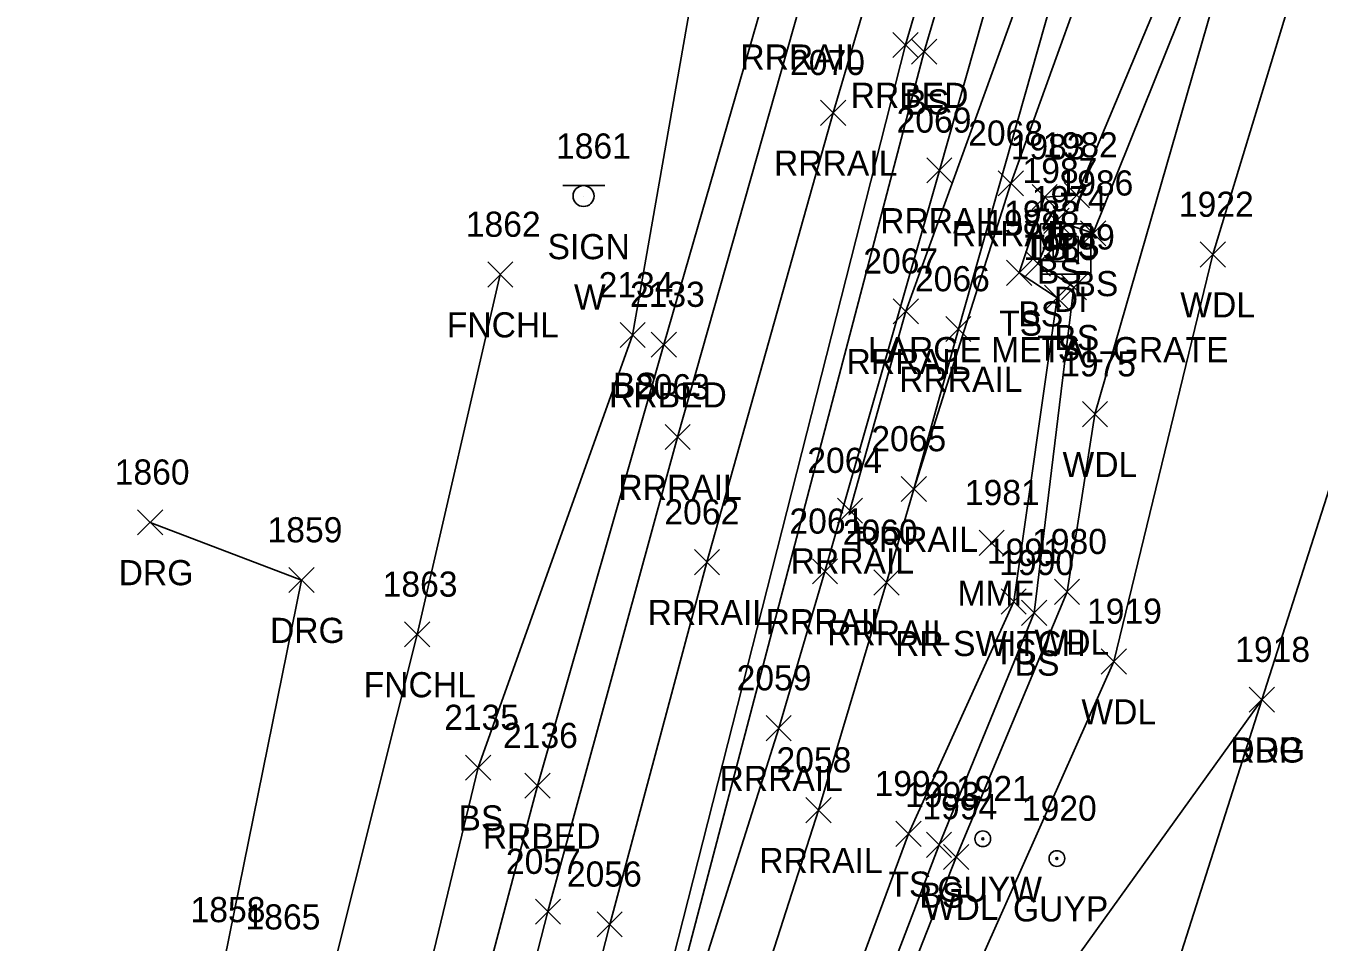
# Model space of a CAD drawing. Extents: x 1769141 to 1770817, y 735471 to 742405.
# Drawn here: x 1770206.1 to 1770309, y 742108.4 to 742181.3 of the extents above; entities that cross this region are included whole.
import ezdxf

# ---------------------------------------------------------------- set-up
doc = ezdxf.new("R2010")
doc.units = 0
for name, color, linetype in [('D_A', 7, 'Continuous'), ('D_C', 7, 'Continuous'), ('D_I', 7, 'Continuous'), ('DS', 7, 'Continuous'), ('L_A', 7, 'Continuous'), ('L_C', 7, 'Continuous'), ('L_I', 7, 'Continuous'), ('L_TIC', 7, 'Continuous'), ('LAWA', 7, 'Continuous'), ('LELB', 7, 'Continuous'), ('LFNC', 7, 'Continuous'), ('P_A', 7, 'Continuous'), ('P_I', 7, 'Continuous'), ('P_TIC', 7, 'Continuous'), ('PET', 7, 'Continuous'), ('R_A', 7, 'Continuous'), ('R_I', 7, 'Continuous'), ('R_TIC', 7, 'Continuous'), ('RDG', 7, 'Continuous'), ('RR', 7, 'Continuous'), ('RRB', 7, 'Continuous'), ('S_A', 7, 'Continuous'), ('S_C', 7, 'Continuous'), ('S_I', 7, 'Continuous'), ('SSGN', 7, 'Continuous'), ('U_A', 7, 'Continuous'), ('U_I', 7, 'Continuous'), ('UPGW', 7, 'Continuous')]:
    doc.layers.add(name, color=color, linetype=linetype)

msp = doc.modelspace()

# ---------------------------------------------------------------- linework, layer by layer
at = {"layer": 'DS'}
for p, q in [((1770286.8, 742165.54), (1770290.8, 742165.54)), ((1770286.8, 742161.54), (1770286.8, 742165.54)), ((1770290.8, 742165.54), (1770290.8, 742161.54)), ((1770287.8, 742162.54), (1770287.8, 742164.54)), ((1770287.8, 742164.54), (1770289.8, 742164.54)), ((1770289.8, 742164.54), (1770289.8, 742162.54)), ((1770288.8, 742163.54), (1770288.8, 742163.54)), ((1770288.8, 742163.54), (1770288.8, 742163.54)), ((1770289.8, 742162.54), (1770287.8, 742162.54)), ((1770290.8, 742161.54), (1770286.8, 742161.54))]:
    msp.add_line(p, q, dxfattribs=at)
at = {"layer": 'L_TIC'}
for points in [[(1770276.55, 742178.23), (1770278.55, 742180.23)], [(1770278.55, 742178.23), (1770276.55, 742180.23)], [(1770286.13, 742166.67), (1770288.13, 742168.67)], [(1770288.13, 742166.67), (1770286.13, 742168.67)], [(1770288.69, 742166.82), (1770290.69, 742168.82)], [(1770290.69, 742166.82), (1770288.69, 742168.82)], [(1770287.07, 742164.78), (1770289.07, 742166.78)], [(1770289.07, 742164.78), (1770287.07, 742166.78)], [(1770289.98, 742163.79), (1770291.98, 742165.79)], [(1770291.98, 742163.79), (1770289.98, 742165.79)], [(1770299.5, 742162.1), (1770301.5, 742164.1)], [(1770301.5, 742162.1), (1770299.5, 742164.1)], [(1770285.6, 742161.38), (1770287.6, 742163.38)], [(1770287.6, 742161.38), (1770285.6, 742163.38)], [(1770242.85, 742160.51), (1770244.85, 742162.51)], [(1770244.85, 742160.51), (1770242.85, 742162.51)], [(1770284.1, 742160.65), (1770286.1, 742162.65)], [(1770286.1, 742160.65), (1770284.1, 742162.65)], [(1770288.46, 742159.5), (1770290.46, 742161.5)], [(1770290.46, 742159.5), (1770288.46, 742161.5)], [(1770287.13, 742158.66), (1770289.13, 742160.66)], [(1770289.13, 742158.66), (1770287.13, 742160.66)], [(1770253.37, 742155.7), (1770255.37, 742157.7)], [(1770255.37, 742155.7), (1770253.37, 742157.7)], [(1770290.13, 742149.41), (1770292.13, 742151.41)], [(1770292.13, 742149.41), (1770290.13, 742151.41)], [(1770281.91, 742139.18), (1770283.91, 742141.18)], [(1770283.91, 742139.18), (1770281.91, 742141.18)], [(1770283.67, 742134.52), (1770285.67, 742136.52)], [(1770285.67, 742134.52), (1770283.67, 742136.52)], [(1770287.91, 742135.29), (1770289.91, 742137.29)], [(1770289.91, 742135.29), (1770287.91, 742137.29)], [(1770285.3, 742133.62), (1770287.3, 742135.62)], [(1770287.3, 742133.62), (1770285.3, 742135.62)], [(1770236.24, 742131.9), (1770238.24, 742133.9)], [(1770238.24, 742131.9), (1770236.24, 742133.9)], [(1770291.63, 742129.75), (1770293.63, 742131.75)], [(1770293.63, 742129.75), (1770291.63, 742131.75)], [(1770241.09, 742121.31), (1770243.09, 742123.31)], [(1770243.09, 742121.31), (1770241.09, 742123.31)], [(1770275.3, 742116.05), (1770277.3, 742118.05)], [(1770277.3, 742116.05), (1770275.3, 742118.05)], [(1770277.73, 742115.17), (1770279.73, 742117.17)], [(1770279.73, 742115.17), (1770277.73, 742117.17)], [(1770279.1, 742114.2), (1770281.1, 742116.2)], [(1770281.1, 742114.2), (1770279.1, 742116.2)]]:
    msp.add_lwpolyline(points, dxfattribs=at)
at = {"layer": 'LAWA'}
msp.add_lwpolyline([(1770278.27, 742098.51), (1770292.63, 742130.75), (1770300.5, 742163.1), (1770310.78, 742196.92), (1770318.92, 742223), (1770331.76, 742252.5), (1770324.85, 742244.64), (1770302.11, 742188.56), (1770291.13, 742150.41), (1770288.91, 742136.29), (1770280.1, 742115.2), (1770273.51, 742098.5)], dxfattribs=at)
at = {"layer": 'LELB'}
for points in [[(1770332.23, 742396.99), (1770317.41, 742358.29), (1770305.3, 742323.67), (1770290.81, 742279.34), (1770278.82, 742239.77), (1770261.32, 742196.43), (1770254.37, 742156.7), (1770242.09, 742122.31), (1770234.14, 742089.37), (1770227.06, 742053.39), (1770219.68, 742019.63), (1770213.36, 741989.97), (1770210.16, 741976.3), (1770206.14, 741961.98)], [(1770380.12, 742366.91), (1770363.06, 742334.87), (1770342.94, 742294.53), (1770326.94, 742263.13), (1770309.84, 742221.71), (1770298.92, 742189.88), (1770289.69, 742167.82), (1770287.13, 742167.67), (1770285.1, 742161.65), (1770288.13, 742159.66), (1770284.67, 742135.52), (1770276.3, 742117.05), (1770269.66, 742099.09), (1770260.58, 742066.82), (1770250.33, 742031.54), (1770242.02, 742000.43), (1770236.09, 741978.68), (1770232.48, 741959.64)], [(1770381.35, 742366.29), (1770364.19, 742334.21), (1770345.62, 742293.81), (1770328.91, 742260.94), (1770312.07, 742221.07), (1770300.68, 742188.95), (1770290.98, 742164.79), (1770288.07, 742165.78), (1770286.6, 742162.38), (1770289.46, 742160.5), (1770286.3, 742134.62), (1770278.73, 742116.17), (1770272.1, 742098.75), (1770262.82, 742065.76), (1770253.59, 742031.78), (1770244.44, 742003.2), (1770237.54, 741978.15), (1770232.48, 741959.64)], [(1770255.17, 742093.88), (1770277.55, 742179.23), (1770295.2, 742239), (1770314.05, 742295.07)]]:
    msp.add_lwpolyline(points, dxfattribs=at)
at = {"layer": 'LFNC'}
msp.add_lwpolyline([(1770243.85, 742161.51), (1770237.24, 742132.9), (1770228.99, 742100.06)], dxfattribs=at)
at = {"layer": 'P_TIC'}
for points in [[(1770303.4, 742126.71), (1770305.4, 742128.71)], [(1770305.4, 742126.71), (1770303.4, 742128.71)]]:
    msp.add_lwpolyline(points, dxfattribs=at)
at = {"layer": 'PET'}
msp.add_lwpolyline([(1770272.7, 742023.54), (1770282.64, 742061.02), (1770293.57, 742093.79), (1770304.4, 742127.71), (1770313.88, 742157.38), (1770333.72, 742213.99), (1770354.85, 742269.34), (1770368.55, 742301.73), (1770378.75, 742329.81), (1770392.05, 742361.37)], dxfattribs=at)
at = {"layer": 'R_TIC'}
for points in [[(1770275.07, 742178.76), (1770277.07, 742180.76)], [(1770277.07, 742178.76), (1770275.07, 742180.76)], [(1770269.31, 742173.37), (1770271.31, 742175.37)], [(1770271.31, 742173.37), (1770269.31, 742175.37)], [(1770277.76, 742168.79), (1770279.76, 742170.79)], [(1770279.76, 742168.79), (1770277.76, 742170.79)], [(1770283.44, 742167.76), (1770285.44, 742169.76)], [(1770285.44, 742167.76), (1770283.44, 742169.76)], [(1770275.09, 742157.59), (1770277.09, 742159.59)], [(1770277.09, 742157.59), (1770275.09, 742159.59)], [(1770279.27, 742156.18), (1770281.27, 742158.18)], [(1770281.27, 742156.18), (1770279.27, 742158.18)], [(1770255.86, 742154.94), (1770257.86, 742156.94)], [(1770257.86, 742154.94), (1770255.86, 742156.94)], [(1770256.95, 742147.59), (1770258.95, 742149.59)], [(1770258.95, 742147.59), (1770256.95, 742149.59)], [(1770275.73, 742143.46), (1770277.73, 742145.46)], [(1770277.73, 742143.46), (1770275.73, 742145.46)], [(1770275.73, 742143.46), (1770277.73, 742145.46)], [(1770277.73, 742143.46), (1770275.73, 742145.46)], [(1770270.65, 742141.74), (1770272.65, 742143.74)], [(1770272.65, 742141.74), (1770270.65, 742143.74)], [(1770215.02, 742140.81), (1770217.02, 742142.81)], [(1770217.02, 742140.81), (1770215.02, 742142.81)], [(1770259.28, 742137.64), (1770261.28, 742139.64)], [(1770261.28, 742137.64), (1770259.28, 742139.64)], [(1770268.66, 742136.91), (1770270.66, 742138.91)], [(1770270.66, 742136.91), (1770268.66, 742138.91)], [(1770227.05, 742136.22), (1770229.05, 742138.22)], [(1770229.05, 742136.22), (1770227.05, 742138.22)], [(1770273.55, 742136.03), (1770275.55, 742138.03)], [(1770275.55, 742136.03), (1770273.55, 742138.03)], [(1770303.4, 742126.71), (1770305.4, 742128.71)], [(1770305.4, 742126.71), (1770303.4, 742128.71)], [(1770264.99, 742124.45), (1770266.99, 742126.45)], [(1770266.99, 742124.45), (1770264.99, 742126.45)], [(1770245.81, 742119.87), (1770247.81, 742121.87)], [(1770247.81, 742119.87), (1770245.81, 742121.87)], [(1770268.15, 742117.93), (1770270.15, 742119.93)], [(1770270.15, 742117.93), (1770268.15, 742119.93)], [(1770246.64, 742109.86), (1770248.64, 742111.86)], [(1770248.64, 742109.86), (1770246.64, 742111.86)], [(1770251.55, 742108.85), (1770253.55, 742110.85)], [(1770253.55, 742108.85), (1770251.55, 742110.85)]]:
    msp.add_lwpolyline(points, dxfattribs=at)
at = {"layer": 'RDG'}
for points in [[(1770207.76, 742033.79), (1770209.12, 742052.49), (1770216.16, 742083.21), (1770221.93, 742107.02), (1770228.05, 742137.22), (1770216.02, 742141.81)], [(1770264.42, 741997.74), (1770265.66, 742027.49), (1770271.5, 742060.44), (1770282.4, 742097.08), (1770304.4, 742127.71)]]:
    msp.add_lwpolyline(points, dxfattribs=at)
at = {"layer": 'RR'}
for points in [[(1770228.86, 742035.21), (1770233.42, 742054.72), (1770238.03, 742073.49), (1770247.64, 742110.86), (1770257.95, 742148.59), (1770267.65, 742182.8), (1770278.27, 742218.42), (1770281.99, 742230.6), (1770291.93, 742261.78), (1770298.46, 742281.94), (1770310.78, 742317.95), (1770323.27, 742353.88), (1770336.53, 742389.56)], [(1770271.65, 742142.74), (1770276.09, 742158.59), (1770294.25, 742208.74), (1770297.09, 742215.37), (1770299.29, 742220.45), (1770313.08, 742250.48), (1770327.36, 742280.38), (1770344.65, 742315.25), (1770362.7, 742349.81), (1770381.95, 742383.73)], [(1770234.04, 742035.58), (1770238.5, 742054.13), (1770247.99, 742091.95), (1770252.55, 742109.85), (1770260.28, 742138.64), (1770270.31, 742174.37), (1770278.8, 742203.12), (1770290.02, 742239.43), (1770296.47, 742259.99), (1770308.47, 742295.99), (1770320.74, 742331.91), (1770333.76, 742367.71)], [(1770276.73, 742144.46), (1770284.44, 742168.76), (1770293.16, 742192.94), (1770306.05, 742223.24), (1770314.75, 742242.2), (1770324.21, 742262.42), (1770341.35, 742297.61), (1770358.95, 742332.23), (1770377.56, 742366.61)], [(1770212.41, 741956.11), (1770215.59, 741972.32), (1770224.21, 742004.12), (1770229.48, 742020.05), (1770231.83, 742026.33), (1770233.36, 742030.93), (1770234.9, 742035.43), (1770245.29, 742063.53), (1770258.11, 742100.47), (1770265.99, 742125.45), (1770269.66, 742137.91), (1770278.76, 742169.79), (1770287.08, 742199.09), (1770296.7, 742230.77), (1770306.54, 742262.18), (1770316.86, 742293.7)], [(1770216.86, 741956.06), (1770220.47, 741971.24), (1770224.73, 741988.15), (1770230.52, 742007.6), (1770241.28, 742038.61), (1770247.11, 742054.33), (1770252.93, 742070.06), (1770259.09, 742087.58), (1770269.15, 742118.93), (1770274.55, 742137.03), (1770276.73, 742144.46), (1770280.27, 742157.18), (1770289.26, 742188.86), (1770295.02, 742208.42), (1770297.09, 742215.37), (1770298.78, 742220.71), (1770308.51, 742252.21), (1770318.64, 742283.66)]]:
    msp.add_lwpolyline(points, dxfattribs=at)
at = {"layer": 'RRB'}
for points in [[(1770334.91, 742396.24), (1770320.98, 742356.43), (1770309.38, 742323.07), (1770294.31, 742278.11), (1770281.7, 742240.39), (1770267.62, 742193.22), (1770256.86, 742155.94), (1770246.81, 742120.87), (1770238.35, 742088.99), (1770231.63, 742060.85), (1770227.63, 742029.05), (1770215.73, 741989.64), (1770208.91, 741960.54)], [(1770219.87, 741959.41), (1770227.39, 741986.94), (1770232.28, 742006.89), (1770240.88, 742038.91), (1770254.48, 742094.84), (1770276.07, 742179.76), (1770293.54, 742239.51), (1770311.55, 742295.01)]]:
    msp.add_lwpolyline(points, dxfattribs=at)
at = {"layer": 'SSGN'}
for p, q in [((1770248.82, 742168.58), (1770252.16, 742168.58)), ((1770250.47, 742167.75), (1770250.47, 742167.75))]:
    msp.add_line(p, q, dxfattribs=at)
msp.add_circle((1770250.47, 742167.75), 0.833, dxfattribs=at)
at = {"layer": 'UPGW'}
for centre, radius in [((1770282.21, 742116.65), 0.625), ((1770282.21, 742116.65), 0.0833), ((1770288.1, 742115.08), 0.625), ((1770288.1, 742115.08), 0.0833)]:
    msp.add_circle(centre, radius, dxfattribs=at)

# ---------------------------------------------------------------- texts
at = {"layer": 'D_A'}
msp.add_text('DI', height=2, dxfattribs=at).set_placement((1770287.86, 742158.54))
at = {"layer": 'D_C'}
msp.add_text('LARGE METAL GRATE', height=2, dxfattribs=at).set_placement((1770273.07, 742154.54))
at = {"layer": 'D_I'}
msp.add_text('1974', height=2, dxfattribs=at).set_placement((1770286.11, 742166.54))
at = {"layer": 'L_A'}
for s, p in [('BS', (1770275.99, 742174.23)), ('TS', (1770285.54, 742162.67)), ('TS', (1770288.09, 742162.82)), ('BS', (1770286.51, 742160.78)), ('BS', (1770289.42, 742159.79)), ('WDL', (1770297.91, 742158.1)), ('BS', (1770285.04, 742157.38)), ('FNCHL', (1770239.6, 742156.51)), ('TS', (1770283.51, 742156.65)), ('BS', (1770287.9, 742155.5)), ('TS', (1770286.54, 742154.66)), ('BS', (1770252.81, 742151.7)), ('WDL', (1770288.55, 742145.41)), ('MMF', (1770280.2, 742135.18)), ('WDL', (1770286.32, 742131.29)), ('TS', (1770283.08, 742130.52)), ('BS', (1770284.74, 742129.62)), ('FNCHL', (1770232.99, 742127.9)), ('WDL', (1770290.05, 742125.75)), ('BS', (1770240.53, 742117.31)), ('TS', (1770274.71, 742112.05)), ('BS', (1770277.17, 742111.17)), ('WDL', (1770277.52, 742110.2))]:
    msp.add_text(s, height=2, dxfattribs=at).set_placement(p)
at = {"layer": 'L_C'}
msp.add_text('RR SWITCH', height=2, dxfattribs=at).set_placement((1770275.24, 742131.18))
at = {"layer": 'L_I'}
for s, p in [('1983', (1770284.43, 742170.67)), ('1982', (1770286.99, 742170.82)), ('1987', (1770285.37, 742168.78)), ('1986', (1770288.23, 742167.79)), ('1988', (1770283.91, 742165.38)), ('1922', (1770297.8, 742166.1)), ('1862', (1770241.11, 742164.51)), ('1984', (1770282.41, 742164.65)), ('1989', (1770286.76, 742163.5)), ('1985', (1770285.43, 742162.66)), ('2134', (1770251.67, 742159.7)), ('1975', (1770288.44, 742153.41)), ('1981', (1770280.79, 742143.18)), ('1991', (1770282.54, 742138.52)), ('1980', (1770286.13, 742139.29)), ('1990', (1770283.52, 742137.62)), ('1863', (1770234.5, 742135.9)), ('1919', (1770290.5, 742133.75)), ('2135', (1770239.39, 742125.31)), ('1992', (1770273.61, 742120.05)), ('1993', (1770276.04, 742119.17)), ('1994', (1770277.41, 742118.2)), ('1865', (1770223.6, 742109.44))]:
    msp.add_text(s, height=2, dxfattribs=at).set_placement(p)
at = {"layer": 'P_A'}
msp.add_text('RDP', height=2, dxfattribs=at).set_placement((1770301.89, 742122.71))
at = {"layer": 'P_I'}
msp.add_text('1918', height=2, dxfattribs=at).set_placement((1770302.28, 742130.71))
at = {"layer": 'R_A'}
for s, p in [('RRRAIL', (1770262.94, 742177.8)), ('RRBED', (1770271.71, 742174.76)), ('RRRAIL', (1770265.61, 742169.37)), ('RRRAIL', (1770274.05, 742164.79)), ('RRRAIL', (1770279.73, 742163.76)), ('RRRAIL', (1770271.38, 742153.59)), ('RRRAIL', (1770275.56, 742152.18)), ('RRBED', (1770252.5, 742150.94)), ('RRRAIL', (1770253.24, 742143.59)), ('RRRAIL', (1770272.02, 742139.46)), ('RRRAIL', (1770272.02, 742139.46)), ('RRRAIL', (1770266.94, 742137.74)), ('DRG', (1770213.51, 742136.81)), ('RRRAIL', (1770255.57, 742133.64)), ('DRG', (1770225.54, 742132.22)), ('RRRAIL', (1770264.95, 742132.91)), ('RRRAIL', (1770269.84, 742132.03)), ('DRG', (1770301.89, 742122.71)), ('RRRAIL', (1770261.28, 742120.45)), ('RRBED', (1770242.46, 742115.87)), ('RRRAIL', (1770264.44, 742113.93))]:
    msp.add_text(s, height=2, dxfattribs=at).set_placement(p)
at = {"layer": 'R_I'}
for s, p in [('2070', (1770266.89, 742177.37)), ('2069', (1770275.36, 742172.79)), ('2068', (1770281.05, 742171.76)), ('2067', (1770272.71, 742161.59)), ('2066', (1770276.82, 742160.18)), ('2133', (1770254.16, 742158.94)), ('2063', (1770254.56, 742151.59)), ('2065', (1770273.35, 742147.46)), ('2065', (1770273.35, 742147.46)), ('2064', (1770268.26, 742145.74)), ('1860', (1770213.2, 742144.81)), ('2062', (1770256.9, 742141.64)), ('2061', (1770266.84, 742140.91)), ('1859', (1770225.35, 742140.22)), ('2060', (1770271.08, 742140.03)), ('1918', (1770302.28, 742130.71)), ('2059', (1770262.64, 742128.45)), ('2136', (1770244.07, 742123.87)), ('2058', (1770265.81, 742121.93)), ('2057', (1770244.3, 742113.86)), ('2056', (1770249.15, 742112.85)), ('1858', (1770219.23, 742110.02))]:
    msp.add_text(s, height=2, dxfattribs=at).set_placement(p)
at = {"layer": 'S_A'}
msp.add_text('SIGN', height=2, dxfattribs=at).set_placement((1770247.61, 742162.73))
at = {"layer": 'S_C'}
msp.add_text('W', height=2, dxfattribs=at).set_placement((1770249.71, 742158.73))
at = {"layer": 'S_I'}
msp.add_text('1861', height=2, dxfattribs=at).set_placement((1770248.28, 742170.73))
at = {"layer": 'U_A'}
for s, p in [('GUYW', (1770278.6, 742111.65)), ('GUYP', (1770284.61, 742110.08))]:
    msp.add_text(s, height=2, dxfattribs=at).set_placement(p)
at = {"layer": 'U_I'}
for s, p in [('1921', (1770280.08, 742119.65)), ('1920', (1770285.32, 742118.08))]:
    msp.add_text(s, height=2, dxfattribs=at).set_placement(p)

doc.saveas('drawing.dxf')
